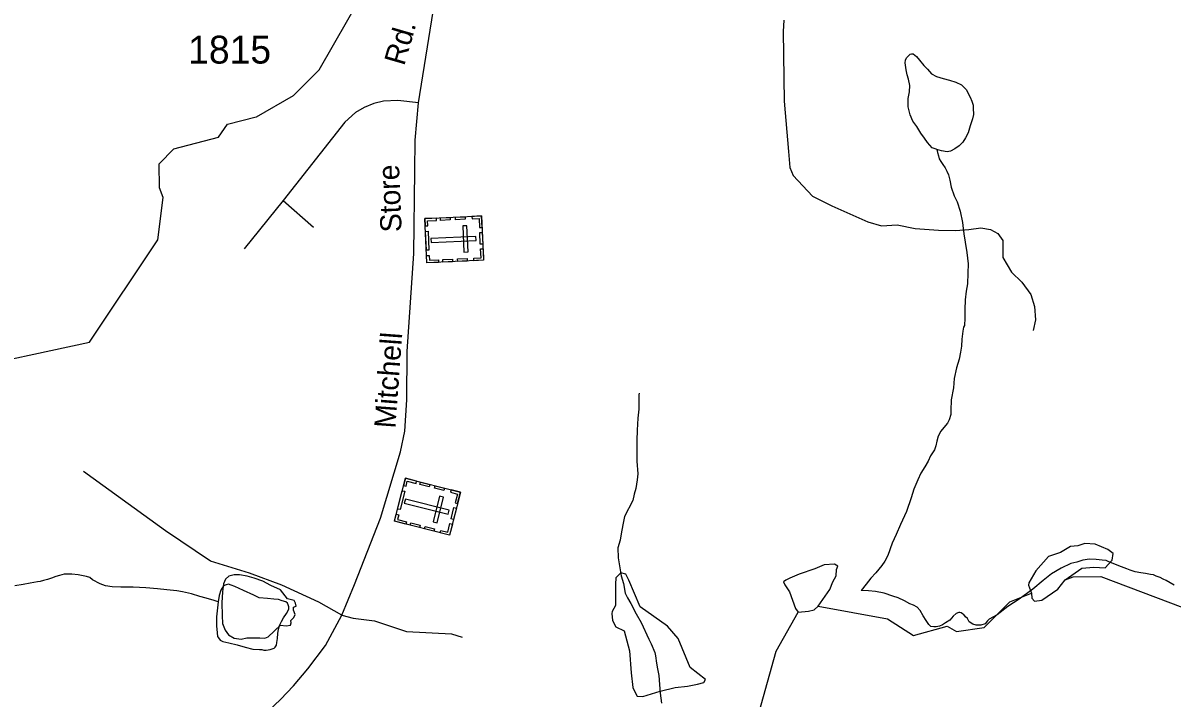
# Model space of a CAD drawing. Extents: x 2126262 to 2293712, y 749403 to 919119.
# Drawn here: x 2184028 to 2189186, y 798369 to 801398 of the extents above; entities that cross this region are included whole.
import ezdxf

# ---------------------------------------------------------------- set-up
doc = ezdxf.new("R2010")
doc.units = 0
for name, color, linetype in [('Exist Cultural Cemetery CELL', 7, 'Continuous'), ('Exist Hydrographic Misc Water Feature', 7, 'Continuous'), ('Exist Hydrographic Pond Under 1500 Sq Ft', 7, 'Continuous'), ('Exist Road Non-System Type 51', 7, 'Continuous'), ('Exist Road Secondary Type 51 Attributed', 7, 'Continuous'), ('Exist Road Secondary Type 51 Label', 7, 'Continuous'), ('Exist Road Secondary Type 51 Number Label', 7, 'Continuous')]:
    doc.layers.add(name, color=color, linetype=linetype)

msp = doc.modelspace()

# ---------------------------------------------------------------- linework, layer by layer
at = {"layer": 'Exist Cultural Cemetery CELL'}
for points in [[(2186084.7, 800531.9), (2186093.8, 800333), (2185839.4, 800321.4), (2185830.3, 800520.3)], [(2185831.9, 800487.2), (2185843.3, 800487.8), (2185842.3, 800509.7), (2185882.7, 800511.6), (2185882.2, 800522.7), (2185830.4, 800520.3)], [(2185900.2, 800523.5), (2185943.4, 800525.5), (2185944, 800514.1), (2185900.7, 800512.1)], [(2185967.3, 800526.6), (2186010.6, 800528.5), (2186011.1, 800517.2), (2185967.8, 800515.2)], [(2186041.4, 800529.9), (2186041.9, 800518.6), (2186074.1, 800520.1), (2186075.9, 800479.5), (2186087.1, 800480.1), (2186084.7, 800531.9)], [(2185844.4, 800463.4), (2185848.3, 800378.6), (2185836.9, 800378.1), (2185833, 800462.9)], [(2186018.6, 800488), (2185999.9, 800487.2), (2186005.3, 800369.6), (2186023.9, 800370.4)], [(2186060.4, 800421.7), (2186059.5, 800440.3), (2185857, 800431), (2185857.8, 800412.4)], [(2186088, 800457.9), (2186090.4, 800406.1), (2186079, 800405.6), (2186076.7, 800457.4)], [(2186050.5, 800331), (2186049.9, 800342.3), (2186082.1, 800343.8), (2186080.2, 800384.3), (2186091.4, 800384.8), (2186093.7, 800333)], [(2185837.9, 800354.5), (2185849.4, 800355), (2185850.4, 800333), (2185890.8, 800334.9), (2185891.3, 800323.8), (2185839.4, 800321.4)], [(2185911.1, 800336), (2185954.4, 800338), (2185954.9, 800326.7), (2185911.6, 800324.7)], [(2185976.9, 800339), (2186020.2, 800341), (2186020.7, 800329.6), (2185977.5, 800327.7)], [(2185989.9, 799292.5), (2185940.9, 799099.5), (2185694.1, 799162.1), (2185743, 799355.1)], [(2185735, 799323), (2185746.1, 799320.2), (2185751.5, 799341.5), (2185790.7, 799331.6), (2185793.4, 799342.4), (2185743.1, 799355.1)], [(2185810.9, 799337.9), (2185852.8, 799327.3), (2185850, 799316.2), (2185808.1, 799326.9)], [(2185740.1, 799296.6), (2185719.2, 799214.3), (2185708.2, 799217.1), (2185729, 799299.4)], [(2185876, 799321.4), (2185918, 799310.7), (2185915.2, 799299.7), (2185873.2, 799310.3)], [(2185947.9, 799303.1), (2185945.1, 799292.1), (2185976.3, 799284.2), (2185966.3, 799244.9), (2185977.1, 799242.2), (2185989.9, 799292.5)], [(2185934.7, 799194), (2185939.3, 799212.1), (2185742.7, 799262), (2185738.1, 799243.9)], [(2185913.9, 799269.7), (2185895.8, 799274.3), (2185866.8, 799160.1), (2185884.9, 799155.5)], [(2185971.6, 799220.7), (2185958.9, 799170.5), (2185947.9, 799173.3), (2185960.6, 799223.5)], [(2185702.3, 799194.2), (2185713.4, 799191.4), (2185708, 799170.1), (2185747.2, 799160.1), (2185744.4, 799149.3), (2185694.1, 799162.1)], [(2185767, 799155.4), (2185808.9, 799144.7), (2185806.2, 799133.7), (2185764.2, 799144.3)], [(2185830.9, 799139.1), (2185872.8, 799128.5), (2185870, 799117.4), (2185828.1, 799128.1)], [(2185898.9, 799110.1), (2185901.7, 799121.1), (2185932.9, 799113.2), (2185942.8, 799152.5), (2185953.6, 799149.8), (2185940.9, 799099.5)]]:
    msp.add_lwpolyline(points, close=True, dxfattribs=at)
at = {"layer": 'Exist Hydrographic Misc Water Feature'}
for points in [[(2185075.6, 800976.6), (2185240.5, 801071.9), (2185356.5, 801187.6), (2185548.8, 801525)], [(2188127, 800830.1), (2188123.1, 800831.9), (2188105.4, 800837.9), (2188085.1, 800861.6), (2188071, 800881.6), (2188054.6, 800903.6), (2188036.8, 800933.4), (2188018.5, 800957.3), (2188006.2, 800985.1), (2187998.2, 801021.2), (2187997.6, 801059), (2188003.5, 801089.4), (2188005.2, 801117.1), (2187999.2, 801145.2), (2187993.3, 801165.2), (2187988.8, 801186.9), (2187986.5, 801209.2), (2187984.9, 801219.2), (2187986.3, 801231.1), (2187990.6, 801241), (2187998.4, 801249.2), (2188006.4, 801257.3), (2188012.8, 801259.2), (2188020.4, 801259.3), (2188034.5, 801247.4), (2188048.4, 801231.5), (2188068.7, 801207.7), (2188084.9, 801189.9), (2188102.8, 801169.7), (2188125.1, 801157.8), (2188154.9, 801148.4), (2188183.4, 801140.5), (2188211.3, 801132.6), (2188237.3, 801120.5), (2188257.6, 801098.9), (2188275.6, 801064.9), (2188283.8, 801047), (2188289.8, 801029.1), (2188290, 801015.3), (2188290.4, 800987.2), (2188286.3, 800967.1), (2188276.5, 800937), (2188267, 800905.1), (2188254.7, 800883), (2188243, 800862.9), (2188227, 800846.6), (2188207.4, 800832.6), (2188187.5, 800822.7), (2188173.3, 800820.3), (2188147.3, 800824.2), (2188127, 800830.1)], [(2185073, 800976), (2185075.6, 800976.6)], [(2183073.5, 799023.5), (2183115.5, 799075.1), (2183106.5, 799173.7), (2183287.6, 799491.4), (2183412.4, 799525), (2183569.5, 799735), (2183727.6, 799836.7), (2184326.6, 799965.4), (2184632.5, 800425), (2184656.5, 800614.8), (2184639.5, 800657.8), (2184638.4, 800766), (2184704.5, 800833.6), (2184904.6, 800885.2), (2184945.6, 800943.4), (2185073, 800976)], [(2188127, 800830.1), (2188129.2, 800816), (2188133.3, 800802.4), (2188137.4, 800788.4), (2188144, 800776.1), (2188153.6, 800762.4), (2188163.5, 800748.3), (2188171.9, 800732.5), (2188178.2, 800716.5), (2188184, 800692.5), (2188190.5, 800660.7), (2188204.7, 800622.8), (2188217, 800595), (2188231.4, 800553.1), (2188241.2, 800502.9), (2188243.7, 800488.8), (2188248, 800451.2), (2188253.9, 800415), (2188260.3, 800367.4), (2188266.8, 800317.3), (2188265, 800275.4), (2188263.3, 800227.3), (2188258, 800195.3), (2188253.9, 800155.4), (2188252.5, 800113), (2188252.7, 800073.2), (2188250.6, 800041.1), (2188246.7, 800033.1), (2188242.4, 800015.1), (2188238.9, 799979.1), (2188237.1, 799947.3), (2188233.2, 799921.1), (2188225.8, 799889), (2188213.9, 799851.1), (2188204.3, 799803), (2188200.6, 799760.9), (2188190.8, 799706.9), (2188189.1, 799658.8), (2188189.5, 799640.9), (2188181.7, 799617), (2188173.9, 799602.8), (2188157.7, 799582.9), (2188144, 799566.7), (2188132.3, 799544.5), (2188126, 799522.3), (2188122.5, 799500.6), (2188116.3, 799482.4), (2188098.5, 799456.3), (2188086.8, 799432.5), (2188073.1, 799406.2), (2188055.2, 799378.1), (2188041.3, 799348.1), (2188023.6, 799305.7), (2188011.7, 799267.8), (2187990.4, 799205.7), (2187962.9, 799147.4), (2187943.3, 799103.3), (2187925.6, 799063.4), (2187905.9, 799009.1), (2187893.8, 798983), (2187880.3, 798963.1), (2187852.4, 798930.8), (2187830.7, 798906.5), (2187808.9, 798880.6), (2187787.2, 798852.3)], [(2186791.3, 799737.1), (2186789.2, 799729.3), (2186789.4, 799707.3), (2186789.6, 799665.1), (2186785.9, 799625.1), (2186782.5, 799571.2), (2186780.6, 799525.2), (2186780.8, 799475.3), (2186781.2, 799431.5), (2186785.9, 799375.2), (2186782, 799347.4), (2186776.3, 799309.3), (2186768.5, 799283.3), (2186762.6, 799255), (2186725, 799183.2), (2186721.3, 799161), (2186711.5, 799115), (2186705.6, 799076.9), (2186695.7, 799042.8), (2186696.5, 798998.8), (2186702.9, 798963), (2186710.9, 798917.1), (2186720.9, 798883.1), (2186729.3, 798839.3), (2186739.2, 798819.1), (2186753.7, 798793.4), (2186777.9, 798747.6), (2186800.1, 798707.7), (2186834.5, 798633.9), (2186845, 798612), (2186861.2, 798573.9), (2186865.3, 798557.9), (2186869.4, 798526), (2186873.5, 798500.2), (2186880.1, 798470), (2186882.3, 798430.4), (2186886.2, 798390.4), (2186890.9, 798346.3)], [(2189190.4, 798875.8), (2189154.3, 798895.9), (2189142, 798901.8), (2189128, 798909.6), (2189110.4, 798915.6), (2189098.1, 798921.5), (2189084, 798923.2), (2189062.2, 798927.3), (2189041.9, 798931.2), (2189015.9, 798934.7), (2188993.7, 798942.9), (2188978.2, 798948.5), (2188942.3, 798962.5), (2188917.5, 798972.3), (2188898, 798980.1), (2188885.9, 798986), (2188867.8, 798987.9), (2188841.6, 798991.4), (2188811.4, 798991.5), (2188781.9, 798987.1), (2188753.8, 798979.2), (2188728, 798972.9), (2188683.9, 798952.4), (2188640.4, 798926.1), (2188602.7, 798896.1), (2188556.8, 798857.6), (2188495, 798813.4), (2188445, 798779.2), (2188397.4, 798742.6), (2188361.8, 798722.4), (2188354, 798716.3), (2188343.9, 798702.4), (2188324.2, 798696), (2188302.1, 798696.1), (2188287.9, 798699.9), (2188271.5, 798711.7), (2188263.8, 798725.8), (2188255.5, 798733.5), (2188248, 798743.6), (2188241.4, 798747.5), (2188235.2, 798751.6), (2188229.7, 798753.3), (2188225.4, 798753.5), (2188213.7, 798749.2), (2188199.8, 798737.1), (2188184, 798719.2), (2188165.7, 798707), (2188151.8, 798696.9), (2188138.1, 798690.9), (2188124.1, 798688.9), (2188112.2, 798688.7), (2188099.7, 798690.6), (2188090.1, 798698.5), (2188078.2, 798716.6), (2188065.7, 798738.4), (2188051.3, 798762.4), (2188037.6, 798776.2), (2188021.4, 798786), (2188005.4, 798792.1), (2187981.2, 798805.9), (2187953.3, 798819.4), (2187929.3, 798825.5), (2187890.8, 798839), (2187850.8, 798846.7), (2187819.2, 798850.6), (2187787.2, 798852.3)], [(2184903.4, 798801.3), (2184885.3, 798807.3), (2184849.6, 798817.1), (2184821.5, 798824.6), (2184783.6, 798836.4), (2184743.4, 798846.1), (2184717.4, 798850.1), (2184673.3, 798853.9), (2184631.5, 798859.8), (2184579.4, 798863.2), (2184521.3, 798867.1), (2184467.2, 798866.8), (2184427.2, 798868.4), (2184397.3, 798872.5), (2184373.5, 798882.2), (2184339.5, 798899.9), (2184327, 798909.9), (2184313.2, 798914), (2184275.5, 798921.7), (2184247.2, 798925.6), (2184213.2, 798925.5), (2184191.2, 798919.1), (2184175.2, 798915), (2184155.3, 798907.1), (2184137.3, 798900.9), (2184119.2, 798896.7), (2184105.3, 798892.7), (2184093, 798890.5), (2184059.8, 798884.6), (2184029.4, 798878.2), (2183991.5, 798872.2)], [(2188701.2, 798899.1), (2188737.4, 798913.5), (2188862.5, 798914.1), (2189229.5, 798775.4)], [(2185087.3, 798818.5), (2185063.3, 798830.2), (2185017.2, 798851.8), (2184977.4, 798869.6), (2184961.2, 798875.3), (2184949.3, 798879.5), (2184939, 798877.4), (2184927.3, 798873.1), (2184915, 798853.4), (2184907.3, 798829.1), (2184903.4, 798801.3)], [(2185088.7, 798586.3), (2185098.8, 798586.3), (2185108.8, 798584.4), (2185118.5, 798584.6), (2185136.7, 798586.7), (2185154.8, 798592.9), (2185158.9, 798596.7), (2185164.8, 798606.8), (2185166.6, 798618.7), (2185168.9, 798636.6), (2185170.3, 798658.7), (2185174.2, 798678.8), (2185178.5, 798694.8), (2185188, 798712.8), (2185196.2, 798729), (2185210.1, 798748.8), (2185215.9, 798758.9), (2185219.8, 798768.9), (2185220, 798772.9), (2185220.2, 798779), (2185217.7, 798787.1), (2185213.8, 798794.9), (2185206, 798800.9), (2185189.6, 798805), (2185173.6, 798810.7), (2185153.5, 798812.5), (2185125.2, 798816.4), (2185087.3, 798818.5)], [(2187594.9, 798782.1), (2187905.5, 798723.9), (2188022.4, 798649.3), (2188172.5, 798692.1), (2188214.5, 798668.4), (2188338.6, 798685.4), (2188454.4, 798801.2), (2188550.7, 798839.4)], [(2184903.4, 798801.3), (2184901.5, 798787.4), (2184896, 798733), (2184896.2, 798693.2), (2184898.4, 798661.3), (2184900.5, 798645.1), (2184904.6, 798639.2), (2184912.2, 798629.5), (2184924.5, 798623.2), (2184950.7, 798617.6), (2184988.5, 798607.8), (2185024.7, 798597.9), (2185058.8, 798588.3), (2185088.7, 798586.3)], [(2185823.9, 795372.1), (2185836.5, 795486), (2185902.6, 795635.5), (2186034.4, 795803.4), (2186308.6, 795945.4), (2186480.4, 796322.4), (2186737.5, 796566.4), (2186894.4, 796776.4), (2187073.4, 797419), (2187071.6, 797642.1), (2187228.4, 797894.7), (2187309.4, 798135.8), (2187309.4, 798237.5), (2187406.4, 798580), (2187504.7, 798753.8)]]:
    msp.add_lwpolyline(points, dxfattribs=at)
at = {"layer": 'Exist Hydrographic Pond Under 1500 Sq Ft'}
for points in [[(2188550.7, 798839.4), (2188551.8, 798817), (2188564.1, 798803.1), (2188598, 798807.7), (2188668.9, 798857.1), (2188701.2, 798899.1), (2188776.9, 798951.2), (2188830.8, 798955.8), (2188881.7, 798952.7), (2188912.5, 798988.2), (2188917.1, 799017.5), (2188894, 799036), (2188837, 799059.2), (2188790.7, 799062.3), (2188758.8, 799052.1), (2188726, 799048.4), (2188681.3, 799022.1), (2188627.3, 799003.6), (2188569.8, 798939.2), (2188539.4, 798886.4), (2188537.9, 798875.6), (2188550.7, 798839.4)], [(2187504.7, 798753.8), (2187550.5, 798759.2), (2187576.3, 798765.6), (2187594.9, 798782.1), (2187646, 798856.1), (2187660.2, 798890.9), (2187674.4, 798918.1), (2187677, 798946.5), (2187682.2, 798960.7), (2187666.7, 798969.8), (2187621.5, 798967.2), (2187579.5, 798948.9), (2187509.1, 798924.5), (2187466.5, 798907.7), (2187448.5, 798898.7), (2187439.4, 798890.9), (2187444.6, 798876.7), (2187465.6, 798845.1), (2187492.4, 798770.8), (2187504.7, 798753.8)], [(2184920.1, 798795.7), (2184921.4, 798739.8), (2184922.3, 798702.9), (2184934, 798673.2), (2184950.2, 798652.5), (2184974.4, 798637.2), (2185005.9, 798633.6), (2185032.1, 798639.8), (2185090.4, 798639), (2185112.9, 798637.2), (2185128.2, 798644.4), (2185182.6, 798695.5), (2185208.1, 798692.6), (2185227.8, 798695.6), (2185231.2, 798706.8), (2185229.8, 798717.3), (2185243.3, 798729.9), (2185248.7, 798744.3), (2185241.5, 798763.2), (2185240.6, 798777.6), (2185253.2, 798782.1), (2185250.5, 798794.7), (2185244.2, 798807.3), (2185213.7, 798813.6), (2185183.1, 798854.1), (2185139.6, 798874.5), (2185103.9, 798892.8), (2185065.3, 798907.2), (2185032.9, 798915.3), (2184998.7, 798921.6), (2184975.3, 798921.6), (2184951.1, 798916.2), (2184935.8, 798901.8), (2184926.8, 798881.1), (2184923.2, 798845.1), (2184920.1, 798795.7)], [(2186708.6, 798930.4), (2186686.8, 798908.5), (2186684.9, 798880.6), (2186684.9, 798783.8), (2186670, 798757.7), (2186668.8, 798748.5), (2186671.9, 798716.7), (2186686.3, 798688.9), (2186724, 798670.2), (2186748.2, 798580.7), (2186755.6, 798482.1), (2186763.1, 798416.9), (2186772.4, 798396.4), (2186781.7, 798377.8), (2186807.8, 798376), (2186885.3, 798400.1), (2186952.9, 798416.9), (2187008.7, 798422.5), (2187053.4, 798431.8), (2187081.3, 798439.3), (2187088.8, 798452.3), (2187019.9, 798506.3), (2186965.9, 798636.7), (2186918.5, 798691.4), (2186796.6, 798778.2), (2186744.5, 798897.4), (2186731.5, 798925.3), (2186708.6, 798930.4)]]:
    msp.add_lwpolyline(points, dxfattribs=at)
at = {"layer": 'Exist Road Non-System Type 51'}
for q in [(2185020.4, 800384), (2185330.2, 800481.3)]:
    msp.add_line((2185194.5, 800601.6), q, dxfattribs=at)
for points in [[(2187439.8, 801410.7), (2187437.2, 801359.5), (2187442.4, 801047.1), (2187461.6, 800820.5), (2187466.7, 800748.9), (2187482.1, 800713), (2187525.6, 800666.9), (2187569.1, 800620.8), (2187656.1, 800577.3), (2187817.4, 800505.6), (2187878.9, 800487.7), (2187948, 800492.8), (2188028.7, 800476.2), (2188133.6, 800468.5), (2188210.4, 800466), (2188269.3, 800471.1), (2188323.1, 800478.8), (2188366.6, 800471.1), (2188399.9, 800453.2), (2188422.9, 800422.4), (2188422.9, 800345.6), (2188461.3, 800279.1), (2188507.4, 800235.5), (2188548.4, 800179.2), (2188563.7, 800125.4), (2188568.9, 800066.6), (2188558.6, 800017.9)], [(2185801.3, 801039.4), (2185709.1, 801049.7), (2185645.1, 801047.1), (2185601.6, 801036.9), (2185558.1, 801019), (2185519.7, 800995.9), (2185471, 800952.4), (2185194.5, 800601.6)], [(2185458.5, 798740.5), (2185354.5, 798798.7), (2185188.5, 798875.6), (2185043.4, 798930), (2184868.3, 798983.8), (2184667.4, 799119.2), (2184499.9, 799240.7), (2184299.7, 799385.3)], [(2185458.5, 798740.5), (2185508.7, 798726.8), (2185605, 798715.7), (2185747.3, 798668.2), (2185949.7, 798657), (2185997.1, 798641.6)]]:
    msp.add_lwpolyline(points, dxfattribs=at)
at = {"layer": 'Exist Road Secondary Type 51 Attributed'}
msp.add_lwpolyline([(2184015, 797418.6), (2184128.8, 797518.5), (2184691.1, 797982.1), (2185049, 798235.6), (2185182.9, 798362.7), (2185241.5, 798424.1), (2185305, 798500.3), (2185384.6, 798605), (2185458.5, 798740.5), (2185515, 798878), (2185631.5, 799176.2), (2185721.5, 799474.3), (2185739.7, 799566.5), (2185748.7, 799706.8), (2185751.5, 799923.3), (2185780.8, 800363.5), (2185785.9, 800734.8), (2185786.7, 800871.6), (2185801.3, 801039.4), (2185893.8, 801618)], dxfattribs=at)

# ---------------------------------------------------------------- texts
at = {"layer": 'Exist Road Secondary Type 51 Label'}
for s, rotation, p in [('Rd.', 73.8488, (2185737.5, 801202.3)), ('Store', 92.3237, (2185726.5, 800460.8)), ('Mitchell', 85.7973, (2185697.7, 799576.9))]:
    msp.add_text(s, height=95, rotation=rotation, dxfattribs=at).set_placement(p)
at = {"layer": 'Exist Road Secondary Type 51 Number Label'}
msp.add_text('1815', height=125, dxfattribs=at).set_placement((2184768.7, 801215.7))

doc.saveas('drawing.dxf')
